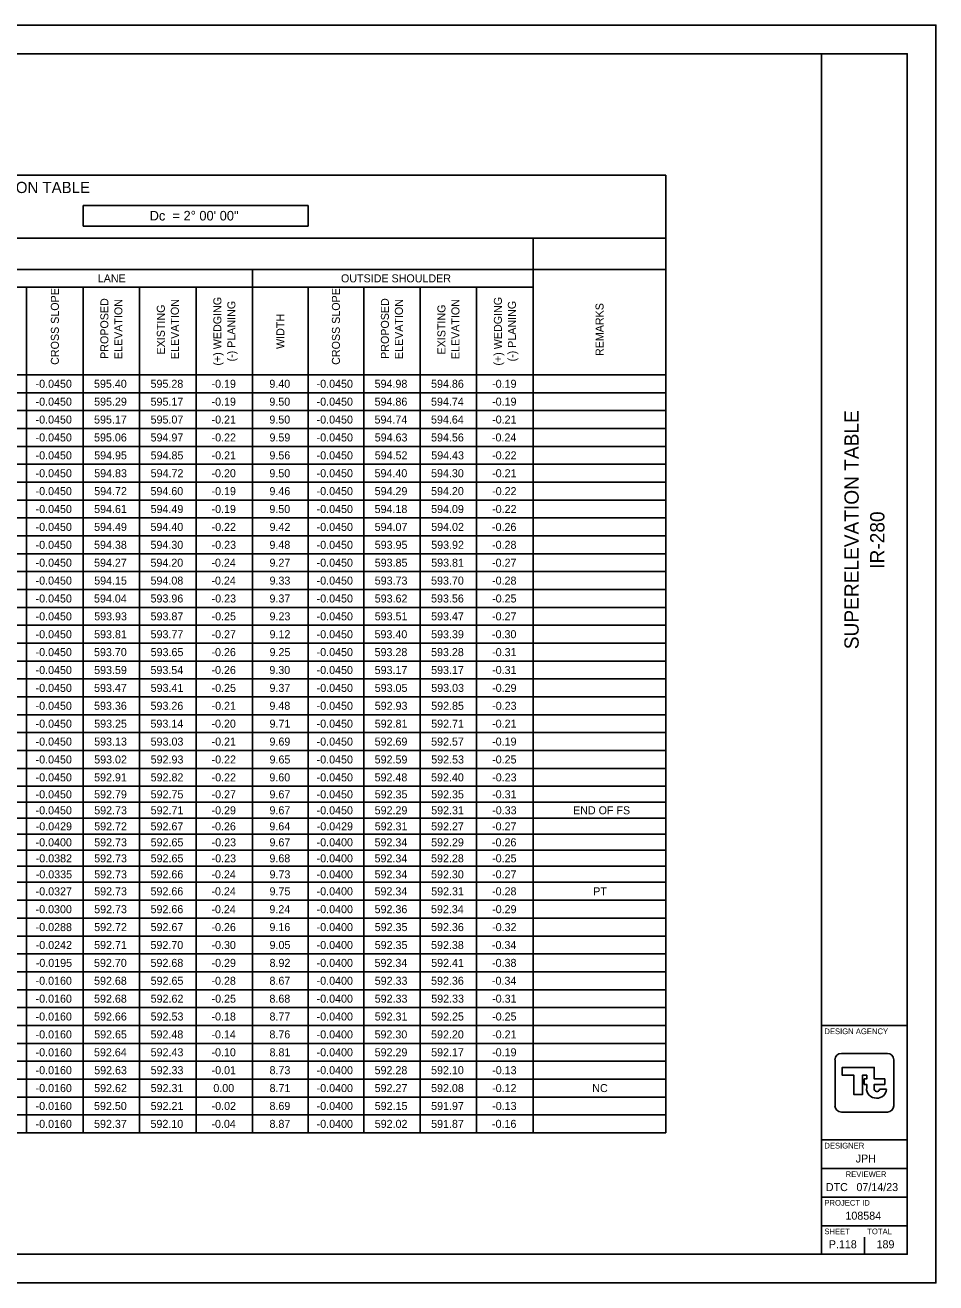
# Model space of a CAD drawing. Extents: x 0 to 34, y 0 to 22.
# Drawn here: x 18.07 to 34, y 0 to 22 of the extents above; entities that cross this region are included whole.
import ezdxf

# ---------------------------------------------------------------- set-up
doc = ezdxf.new("R2010")
doc.units = 0
for name, color, linetype in [('SH_Border', 7, 'Continuous'), ('SH_Cut_Line', 7, 'Continuous'), ('SH_Data', 7, 'Continuous'), ('SH_Text', 7, 'Continuous')]:
    doc.layers.add(name, color=color, linetype=linetype)

msp = doc.modelspace()

# ---------------------------------------------------------------- linework, layer by layer
at = {"layer": 'SH_Border'}
for p, q in [((32, 0.5), (32, 21.5)), ((32, 4.5), (33.5, 4.5)), ((32, 2.5), (33.5, 2.5)), ((32, 2), (33.5, 2)), ((32, 1.5), (33.5, 1.5)), ((32, 1), (33.5, 1))]:
    msp.add_line(p, q, dxfattribs=at)
msp.add_lwpolyline([(1.5, 21.5), (33.5, 21.5), (33.5, 0.5), (1.5, 0.5)], close=True, dxfattribs=at)
at = {"layer": 'SH_Cut_Line'}
msp.add_lwpolyline([(0, 0), (34, 0), (34, 22), (0, 22)], close=True, dxfattribs=at)
at = {"layer": 'SH_Data'}
for p, q in [((32.75, 3.5), (32.75, 3.5)), ((32.791, 3.415), (32.791, 3.415)), ((33.136, 3.385), (33.015, 3.385)), ((32.375, 0.675), (32.375, 0.675)), ((32.75, 0.5), (32.75, 0.8))]:
    msp.add_line(p, q, dxfattribs=at)
for points in [[(32.348, 4.014), (33.152, 4.014)], [(32.236, 3.099), (32.236, 3.901)], [(32.922, 3.399), (32.922, 3.47), (33.107, 3.47), (33.107, 3.568), (32.922, 3.568), (32.922, 3.768), (32.361, 3.768), (32.361, 3.632), (32.566, 3.632), (32.566, 3.294), (32.715, 3.294), (32.715, 3.63), (32.79, 3.63), (32.79, 3.568), (32.748, 3.568), (32.748, 3.47), (32.79, 3.47), (32.79, 3.415), (32.791, 3.415)], [(33.264, 3.901), (33.264, 3.099)], [(33.152, 2.986), (32.348, 2.986)]]:
    msp.add_lwpolyline(points, dxfattribs=at)
for centre, radius, start, end in [((32.348, 3.901), 0.113, 90, 180), ((33.152, 3.901), 0.113, 360, 90), ((32.949, 3.392), 0.16, 171.8856, 274.8323), ((32.968, 3.392), 0.0473, 171.8856, 350.9243), ((32.976, 3.392), 0.16, 265.1677, 357.3201), ((32.348, 3.099), 0.113, 180, 270), ((33.152, 3.099), 0.113, 270, 360)]:
    msp.add_arc(centre, radius, start, end, dxfattribs=at)
at = {"layer": 'SH_Text'}
for p, q in [((4.225, 19.375), (29.277, 19.375)), ((29.277, 19.375), (29.277, 2.624)), ((19.081, 18.848), (23.018, 18.848)), ((19.081, 18.848), (19.081, 18.486)), ((23.018, 18.848), (23.018, 18.486)), ((19.081, 18.486), (23.018, 18.486)), ((4.225, 18.271), (29.277, 18.271)), ((26.954, 18.271), (26.954, 2.624)), ((4.225, 17.728), (29.277, 17.728)), ((22.046, 17.728), (22.046, 2.624)), ((6.317, 17.415), (26.954, 17.415)), ((18.093, 17.415), (18.093, 2.624)), ((19.081, 17.415), (19.081, 2.624)), ((20.07, 17.415), (20.07, 2.624)), ((21.058, 17.415), (21.058, 2.624)), ((23.018, 17.415), (23.018, 2.624)), ((23.99, 17.415), (23.99, 2.624)), ((24.978, 17.415), (24.978, 2.624)), ((25.966, 17.415), (25.966, 2.624)), ((4.225, 15.883), (29.277, 15.883)), ((4.225, 15.57), (29.277, 15.57)), ((4.225, 15.257), (29.277, 15.257)), ((4.225, 14.944), (29.277, 14.944)), ((4.225, 14.631), (29.277, 14.631)), ((4.225, 14.319), (29.277, 14.319)), ((4.225, 14.006), (29.277, 14.006)), ((4.225, 13.693), (29.277, 13.693)), ((4.225, 13.38), (29.277, 13.38)), ((4.225, 13.067), (29.277, 13.067)), ((4.225, 12.754), (29.277, 12.754)), ((4.225, 12.441), (29.277, 12.441)), ((4.225, 12.128), (29.277, 12.128)), ((4.225, 11.815), (29.277, 11.815)), ((4.225, 11.502), (29.277, 11.502)), ((4.225, 11.189), (29.277, 11.189)), ((4.225, 10.876), (29.277, 10.876)), ((4.225, 10.563), (29.277, 10.563)), ((4.225, 10.25), (29.277, 10.25)), ((4.225, 9.937), (29.277, 9.937)), ((4.225, 9.624), (29.277, 9.624)), ((4.225, 9.311), (29.277, 9.311)), ((4.225, 8.999), (29.277, 8.999)), ((4.225, 8.686), (29.277, 8.686)), ((4.225, 8.406), (29.277, 8.406)), ((4.225, 8.126), (29.277, 8.126)), ((4.225, 7.846), (29.277, 7.846)), ((4.225, 7.566), (29.277, 7.566)), ((4.225, 7.286), (29.277, 7.286)), ((4.225, 7.006), (29.277, 7.006)), ((4.225, 6.693), (29.277, 6.693)), ((4.225, 6.38), (29.277, 6.38)), ((4.225, 6.067), (29.277, 6.067)), ((4.225, 5.754), (29.277, 5.754)), ((4.225, 5.441), (29.277, 5.441)), ((4.225, 5.128), (29.277, 5.128)), ((4.225, 4.815), (29.277, 4.815)), ((4.225, 4.502), (29.277, 4.502)), ((4.225, 4.189), (29.277, 4.189)), ((4.225, 3.876), (29.277, 3.876)), ((4.225, 3.563), (29.277, 3.563)), ((4.225, 3.25), (29.277, 3.25)), ((4.225, 2.937), (29.277, 2.937)), ((4.225, 2.624), (29.277, 2.624))]:
    msp.add_line(p, q, dxfattribs=at)

# ---------------------------------------------------------------- texts
at = {"layer": 'SH_Data'}
for s, p in [('SUPERELEVATION TABLE', (32.65, 11.084)), ('IR-280', (33.1, 12.491))]:
    msp.add_text(s, height=0.25, rotation=90, dxfattribs=at).set_placement(p)
for s, height, p in [('DESIGN AGENCY', 0.1, (32.05, 4.35)), ('DESIGNER', 0.1, (32.05, 2.35)), ('JPH', 0.14, (32.598, 2.105)), ('REVIEWER', 0.1, (32.422, 1.85)), ('DTC', 0.14, (32.076, 1.605)), ('07/14/23', 0.14, (32.611, 1.605)), ('PROJECT ID', 0.1, (32.05, 1.35)), ('108584', 0.14, (32.418, 1.105)), ('SHEET', 0.1, (32.05, 0.85)), ('TOTAL', 0.1, (32.8, 0.85)), ('P.118', 0.14, (32.127, 0.605)), ('189', 0.14, (32.963, 0.605))]:
    msp.add_text(s, height=height, dxfattribs=at).set_placement(p)
at = {"layer": 'SH_Text'}
for s, height, p in [('WOO/LUC-280-06.20/00.00 - SUPERELEVATION TABLE', 0.196, (12.442, 19.063)), ('Dc  = 2° 00\' 00"', 0.168, (20.245, 18.583)), ('LANE', 0.14, (19.338, 17.501)), ('OUTSIDE SHOULDER', 0.14, (23.593, 17.501)), ('-0.0450', 0.14, (18.25, 15.657)), ('595.40', 0.14, (19.272, 15.657)), ('595.28', 0.14, (20.261, 15.657)), ('-0.19', 0.14, (21.328, 15.657)), ('9.40', 0.14, (22.34, 15.657)), ('-0.0450', 0.14, (23.167, 15.657)), ('594.98', 0.14, (24.181, 15.657)), ('594.86', 0.14, (25.169, 15.657)), ('-0.19', 0.14, (26.237, 15.657)), ('-0.0450', 0.14, (18.25, 15.344)), ('595.29', 0.14, (19.274, 15.344)), ('595.17', 0.14, (20.262, 15.344)), ('-0.19', 0.14, (21.328, 15.344)), ('9.50', 0.14, (22.34, 15.344)), ('-0.0450', 0.14, (23.167, 15.344)), ('594.86', 0.14, (24.181, 15.344)), ('594.74', 0.14, (25.168, 15.344)), ('-0.19', 0.14, (26.237, 15.344)), ('-0.0450', 0.14, (18.25, 15.031)), ('595.17', 0.14, (19.273, 15.031)), ('595.07', 0.14, (20.262, 15.031)), ('-0.21', 0.14, (21.329, 15.031)), ('9.50', 0.14, (22.34, 15.031)), ('-0.0450', 0.14, (23.167, 15.031)), ('594.74', 0.14, (24.18, 15.031)), ('594.64', 0.14, (25.168, 15.031)), ('-0.21', 0.14, (26.237, 15.031)), ('-0.0450', 0.14, (18.25, 14.718)), ('595.06', 0.14, (19.273, 14.718)), ('594.97', 0.14, (20.262, 14.718)), ('-0.22', 0.14, (21.329, 14.718)), ('9.59', 0.14, (22.342, 14.718)), ('-0.0450', 0.14, (23.167, 14.718)), ('594.63', 0.14, (24.183, 14.718)), ('594.56', 0.14, (25.169, 14.718)), ('-0.24', 0.14, (26.234, 14.718)), ('-0.0450', 0.14, (18.25, 14.405)), ('594.95', 0.14, (19.275, 14.405)), ('594.85', 0.14, (20.263, 14.405)), ('-0.21', 0.14, (21.329, 14.405)), ('9.56', 0.14, (22.341, 14.405)), ('-0.0450', 0.14, (23.167, 14.405)), ('594.52', 0.14, (24.183, 14.405)), ('594.43', 0.14, (25.172, 14.405)), ('-0.22', 0.14, (26.237, 14.405)), ('-0.0450', 0.14, (18.25, 14.092)), ('594.83', 0.14, (19.275, 14.092)), ('594.72', 0.14, (20.263, 14.092)), ('-0.20', 0.14, (21.327, 14.092)), ('9.50', 0.14, (22.34, 14.092)), ('-0.0450', 0.14, (23.167, 14.092)), ('594.40', 0.14, (24.18, 14.092)), ('594.30', 0.14, (25.169, 14.092)), ('-0.21', 0.14, (26.237, 14.092)), ('-0.0450', 0.14, (18.25, 13.779)), ('594.72', 0.14, (19.275, 13.779)), ('594.60', 0.14, (20.26, 13.779)), ('-0.19', 0.14, (21.328, 13.779)), ('9.46', 0.14, (22.341, 13.779)), ('-0.0450', 0.14, (23.167, 13.779)), ('594.29', 0.14, (24.182, 13.779)), ('594.20', 0.14, (25.169, 13.779)), ('-0.22', 0.14, (26.237, 13.779)), ('-0.0450', 0.14, (18.25, 13.466)), ('594.61', 0.14, (19.274, 13.466)), ('594.49', 0.14, (20.262, 13.466)), ('-0.19', 0.14, (21.328, 13.466)), ('9.50', 0.14, (22.34, 13.466)), ('-0.0450', 0.14, (23.167, 13.466)), ('594.18', 0.14, (24.181, 13.466)), ('594.09', 0.14, (25.17, 13.466)), ('-0.22', 0.14, (26.237, 13.466)), ('-0.0450', 0.14, (18.25, 13.153)), ('594.49', 0.14, (19.274, 13.153)), ('594.40', 0.14, (20.26, 13.153)), ('-0.22', 0.14, (21.329, 13.153)), ('9.42', 0.14, (22.343, 13.153)), ('-0.0450', 0.14, (23.167, 13.153)), ('594.07', 0.14, (24.182, 13.153)), ('594.02', 0.14, (25.171, 13.153)), ('-0.26', 0.14, (26.235, 13.153)), ('-0.0450', 0.14, (18.25, 12.84)), ('594.38', 0.14, (19.273, 12.84)), ('594.30', 0.14, (20.26, 12.84)), ('-0.23', 0.14, (21.33, 12.84)), ('9.48', 0.14, (22.341, 12.84)), ('-0.0450', 0.14, (23.167, 12.84)), ('593.95', 0.14, (24.183, 12.84)), ('593.92', 0.14, (25.171, 12.84)), ('-0.28', 0.14, (26.236, 12.84)), ('-0.0450', 0.14, (18.25, 12.527)), ('594.27', 0.14, (19.273, 12.527)), ('594.20', 0.14, (20.26, 12.527)), ('-0.24', 0.14, (21.326, 12.527)), ('9.27', 0.14, (22.342, 12.527)), ('-0.0450', 0.14, (23.167, 12.527)), ('593.85', 0.14, (24.183, 12.527)), ('593.81', 0.14, (25.171, 12.527)), ('-0.27', 0.14, (26.236, 12.527)), ('-0.0450', 0.14, (18.25, 12.214)), ('594.15', 0.14, (19.275, 12.214)), ('594.08', 0.14, (20.261, 12.214)), ('-0.24', 0.14, (21.326, 12.214)), ('9.33', 0.14, (22.343, 12.214)), ('-0.0450', 0.14, (23.167, 12.214)), ('593.73', 0.14, (24.183, 12.214)), ('593.70', 0.14, (25.169, 12.214)), ('-0.28', 0.14, (26.236, 12.214)), ('-0.0450', 0.14, (18.25, 11.901)), ('594.04', 0.14, (19.272, 11.901)), ('593.96', 0.14, (20.261, 11.901)), ('-0.23', 0.14, (21.33, 11.901)), ('9.37', 0.14, (22.342, 11.901)), ('-0.0450', 0.14, (23.167, 11.901)), ('593.62', 0.14, (24.183, 11.901)), ('593.56', 0.14, (25.169, 11.901)), ('-0.25', 0.14, (26.237, 11.901)), ('-0.0450', 0.14, (18.25, 11.589)), ('593.93', 0.14, (19.275, 11.589)), ('593.87', 0.14, (20.262, 11.589)), ('-0.25', 0.14, (21.329, 11.589)), ('9.23', 0.14, (22.343, 11.589)), ('-0.0450', 0.14, (23.167, 11.589)), ('593.51', 0.14, (24.183, 11.589)), ('593.47', 0.14, (25.17, 11.589)), ('-0.27', 0.14, (26.236, 11.589)), ('-0.0450', 0.14, (18.25, 11.276)), ('593.81', 0.14, (19.274, 11.276)), ('593.77', 0.14, (20.262, 11.276)), ('-0.27', 0.14, (21.328, 11.276)), ('9.12', 0.14, (22.343, 11.276)), ('-0.0450', 0.14, (23.167, 11.276)), ('593.40', 0.14, (24.18, 11.276)), ('593.39', 0.14, (25.17, 11.276)), ('-0.30', 0.14, (26.235, 11.276)), ('-0.0450', 0.14, (18.25, 10.963)), ('593.70', 0.14, (19.272, 10.963)), ('593.65', 0.14, (20.263, 10.963)), ('-0.26', 0.14, (21.327, 10.963)), ('9.25', 0.14, (22.343, 10.963)), ('-0.0450', 0.14, (23.167, 10.963)), ('593.28', 0.14, (24.181, 10.963)), ('593.28', 0.14, (25.169, 10.963)), ('-0.31', 0.14, (26.237, 10.963)), ('-0.0450', 0.14, (18.25, 10.65)), ('593.59', 0.14, (19.274, 10.65)), ('593.54', 0.14, (20.26, 10.65)), ('-0.26', 0.14, (21.327, 10.65)), ('9.30', 0.14, (22.34, 10.65)), ('-0.0450', 0.14, (23.167, 10.65)), ('593.17', 0.14, (24.182, 10.65)), ('593.17', 0.14, (25.17, 10.65)), ('-0.31', 0.14, (26.237, 10.65)), ('-0.0450', 0.14, (18.25, 10.337)), ('593.47', 0.14, (19.273, 10.337)), ('593.41', 0.14, (20.263, 10.337)), ('-0.25', 0.14, (21.329, 10.337)), ('9.37', 0.14, (22.342, 10.337)), ('-0.0450', 0.14, (23.167, 10.337)), ('593.05', 0.14, (24.183, 10.337)), ('593.03', 0.14, (25.172, 10.337)), ('-0.29', 0.14, (26.237, 10.337)), ('-0.0450', 0.14, (18.25, 10.024)), ('593.36', 0.14, (19.273, 10.024)), ('593.26', 0.14, (20.261, 10.024)), ('-0.21', 0.14, (21.329, 10.024)), ('9.48', 0.14, (22.341, 10.024)), ('-0.0450', 0.14, (23.167, 10.024)), ('592.93', 0.14, (24.183, 10.024)), ('592.85', 0.14, (25.171, 10.024)), ('-0.23', 0.14, (26.238, 10.024)), ('-0.0450', 0.14, (18.25, 9.711)), ('593.25', 0.14, (19.275, 9.711)), ('593.14', 0.14, (20.26, 9.711)), ('-0.20', 0.14, (21.327, 9.711)), ('9.71', 0.14, (22.343, 9.711)), ('-0.0450', 0.14, (23.167, 9.711)), ('592.81', 0.14, (24.183, 9.711)), ('592.71', 0.14, (25.171, 9.711)), ('-0.21', 0.14, (26.237, 9.711)), ('-0.0450', 0.14, (18.25, 9.398)), ('593.13', 0.14, (19.275, 9.398)), ('593.03', 0.14, (20.263, 9.398)), ('-0.21', 0.14, (21.329, 9.398)), ('9.69', 0.14, (22.342, 9.398)), ('-0.0450', 0.14, (23.167, 9.398)), ('592.69', 0.14, (24.182, 9.398)), ('592.57', 0.14, (25.17, 9.398)), ('-0.19', 0.14, (26.237, 9.398)), ('-0.0450', 0.14, (18.25, 9.085)), ('593.02', 0.14, (19.275, 9.085)), ('592.93', 0.14, (20.263, 9.085)), ('-0.22', 0.14, (21.329, 9.085)), ('9.65', 0.14, (22.343, 9.085)), ('-0.0450', 0.14, (23.167, 9.085)), ('592.59', 0.14, (24.182, 9.085)), ('592.53', 0.14, (25.172, 9.085)), ('-0.25', 0.14, (26.237, 9.085)), ('-0.0450', 0.14, (18.25, 8.772)), ('592.91', 0.14, (19.274, 8.772)), ('592.82', 0.14, (20.263, 8.772)), ('-0.22', 0.14, (21.329, 8.772)), ('9.60', 0.14, (22.34, 8.772)), ('-0.0450', 0.14, (23.167, 8.772)), ('592.48', 0.14, (24.181, 8.772)), ('592.40', 0.14, (25.169, 8.772)), ('-0.23', 0.14, (26.238, 8.772)), ('-0.0450', 0.14, (18.25, 8.476)), ('592.79', 0.14, (19.274, 8.476)), ('592.75', 0.14, (20.263, 8.476)), ('-0.27', 0.14, (21.328, 8.476)), ('9.67', 0.14, (22.342, 8.476)), ('-0.0450', 0.14, (23.167, 8.476)), ('592.35', 0.14, (24.183, 8.476)), ('592.35', 0.14, (25.171, 8.476)), ('-0.31', 0.14, (26.237, 8.476)), ('-0.0450', 0.14, (18.25, 8.196)), ('592.73', 0.14, (19.275, 8.196)), ('592.71', 0.14, (20.263, 8.196)), ('-0.29', 0.14, (21.328, 8.196)), ('9.67', 0.14, (22.342, 8.196)), ('-0.0450', 0.14, (23.167, 8.196)), ('592.29', 0.14, (24.182, 8.196)), ('592.31', 0.14, (25.171, 8.196)), ('-0.33', 0.14, (26.238, 8.196)), ('END OF FS', 0.14, (27.653, 8.196)), ('-0.0429', 0.14, (18.252, 7.916)), ('592.72', 0.14, (19.275, 7.916)), ('592.67', 0.14, (20.262, 7.916)), ('-0.26', 0.14, (21.327, 7.916)), ('9.64', 0.14, (22.34, 7.916)), ('-0.0429', 0.14, (23.168, 7.916)), ('592.31', 0.14, (24.183, 7.916)), ('592.27', 0.14, (25.17, 7.916)), ('-0.27', 0.14, (26.236, 7.916)), ('-0.0400', 0.14, (18.25, 7.636)), ('592.73', 0.14, (19.275, 7.636)), ('592.65', 0.14, (20.263, 7.636)), ('-0.23', 0.14, (21.33, 7.636)), ('9.67', 0.14, (22.342, 7.636)), ('-0.0400', 0.14, (23.167, 7.636)), ('592.34', 0.14, (24.18, 7.636)), ('592.29', 0.14, (25.17, 7.636)), ('-0.26', 0.14, (26.235, 7.636)), ('-0.0382', 0.14, (18.252, 7.356)), ('592.73', 0.14, (19.275, 7.356)), ('592.65', 0.14, (20.263, 7.356)), ('-0.23', 0.14, (21.33, 7.356)), ('9.68', 0.14, (22.341, 7.356)), ('-0.0400', 0.14, (23.167, 7.356)), ('592.34', 0.14, (24.18, 7.356)), ('592.28', 0.14, (25.169, 7.356)), ('-0.25', 0.14, (26.237, 7.356)), ('-0.0335', 0.14, (18.253, 7.076)), ('592.73', 0.14, (19.275, 7.076)), ('592.66', 0.14, (20.261, 7.076)), ('-0.24', 0.14, (21.326, 7.076)), ('9.73', 0.14, (22.343, 7.076)), ('-0.0400', 0.14, (23.167, 7.076)), ('592.34', 0.14, (24.18, 7.076)), ('592.30', 0.14, (25.169, 7.076)), ('-0.27', 0.14, (26.236, 7.076)), ('-0.0327', 0.14, (18.251, 6.779)), ('592.73', 0.14, (19.275, 6.779)), ('592.66', 0.14, (20.261, 6.779)), ('-0.24', 0.14, (21.326, 6.779)), ('9.75', 0.14, (22.343, 6.779)), ('-0.0400', 0.14, (23.167, 6.779)), ('592.34', 0.14, (24.18, 6.779)), ('592.31', 0.14, (25.171, 6.779)), ('-0.28', 0.14, (26.236, 6.779)), ('PT', 0.14, (28.006, 6.779)), ('-0.0300', 0.14, (18.25, 6.466)), ('592.73', 0.14, (19.275, 6.466)), ('592.66', 0.14, (20.261, 6.466)), ('-0.24', 0.14, (21.326, 6.466)), ('9.24', 0.14, (22.34, 6.466)), ('-0.0400', 0.14, (23.167, 6.466)), ('592.36', 0.14, (24.181, 6.466)), ('592.34', 0.14, (25.168, 6.466)), ('-0.29', 0.14, (26.237, 6.466)), ('-0.0288', 0.14, (18.251, 6.153)), ('592.72', 0.14, (19.275, 6.153)), ('592.67', 0.14, (20.262, 6.153)), ('-0.26', 0.14, (21.327, 6.153)), ('9.16', 0.14, (22.341, 6.153)), ('-0.0400', 0.14, (23.167, 6.153)), ('592.35', 0.14, (24.183, 6.153)), ('592.36', 0.14, (25.169, 6.153)), ('-0.32', 0.14, (26.237, 6.153)), ('-0.0242', 0.14, (18.252, 5.84)), ('592.71', 0.14, (19.274, 5.84)), ('592.70', 0.14, (20.26, 5.84)), ('-0.30', 0.14, (21.327, 5.84)), ('9.05', 0.14, (22.343, 5.84)), ('-0.0400', 0.14, (23.167, 5.84)), ('592.35', 0.14, (24.183, 5.84)), ('592.38', 0.14, (25.169, 5.84)), ('-0.34', 0.14, (26.234, 5.84)), ('-0.0195', 0.14, (18.253, 5.527)), ('592.70', 0.14, (19.272, 5.527)), ('592.68', 0.14, (20.261, 5.527)), ('-0.29', 0.14, (21.328, 5.527)), ('8.92', 0.14, (22.343, 5.527)), ('-0.0400', 0.14, (23.167, 5.527)), ('592.34', 0.14, (24.18, 5.527)), ('592.41', 0.14, (25.171, 5.527)), ('-0.38', 0.14, (26.236, 5.527)), ('-0.0160', 0.14, (18.25, 5.214)), ('592.68', 0.14, (19.273, 5.214)), ('592.65', 0.14, (20.263, 5.214)), ('-0.28', 0.14, (21.327, 5.214)), ('8.67', 0.14, (22.342, 5.214)), ('-0.0400', 0.14, (23.167, 5.214)), ('592.33', 0.14, (24.183, 5.214)), ('592.36', 0.14, (25.169, 5.214)), ('-0.34', 0.14, (26.234, 5.214)), ('-0.0160', 0.14, (18.25, 4.901)), ('592.68', 0.14, (19.273, 4.901)), ('592.62', 0.14, (20.263, 4.901)), ('-0.25', 0.14, (21.329, 4.901)), ('8.68', 0.14, (22.341, 4.901)), ('-0.0400', 0.14, (23.167, 4.901)), ('592.33', 0.14, (24.183, 4.901)), ('592.33', 0.14, (25.172, 4.901)), ('-0.31', 0.14, (26.237, 4.901)), ('-0.0160', 0.14, (18.25, 4.589)), ('592.66', 0.14, (19.273, 4.589)), ('592.53', 0.14, (20.263, 4.589)), ('-0.18', 0.14, (21.327, 4.589)), ('8.77', 0.14, (22.342, 4.589)), ('-0.0400', 0.14, (23.167, 4.589)), ('592.31', 0.14, (24.183, 4.589)), ('592.25', 0.14, (25.171, 4.589)), ('-0.25', 0.14, (26.237, 4.589)), ('-0.0160', 0.14, (18.25, 4.276)), ('592.65', 0.14, (19.275, 4.276)), ('592.48', 0.14, (20.261, 4.276)), ('-0.14', 0.14, (21.326, 4.276)), ('8.76', 0.14, (22.341, 4.276)), ('-0.0400', 0.14, (23.167, 4.276)), ('592.30', 0.14, (24.18, 4.276)), ('592.20', 0.14, (25.169, 4.276)), ('-0.21', 0.14, (26.237, 4.276)), ('-0.0160', 0.14, (18.25, 3.963)), ('592.64', 0.14, (19.272, 3.963)), ('592.43', 0.14, (20.263, 3.963)), ('-0.10', 0.14, (21.327, 3.963)), ('8.81', 0.14, (22.343, 3.963)), ('-0.0400', 0.14, (23.167, 3.963)), ('592.29', 0.14, (24.182, 3.963)), ('592.17', 0.14, (25.17, 3.963)), ('-0.19', 0.14, (26.237, 3.963)), ('-0.0160', 0.14, (18.25, 3.65)), ('592.63', 0.14, (19.275, 3.65)), ('592.33', 0.14, (20.263, 3.65)), ('-0.01', 0.14, (21.329, 3.65)), ('8.73', 0.14, (22.343, 3.65)), ('-0.0400', 0.14, (23.167, 3.65)), ('592.28', 0.14, (24.181, 3.65)), ('592.10', 0.14, (25.169, 3.65)), ('-0.13', 0.14, (26.238, 3.65)), ('-0.0160', 0.14, (18.25, 3.337)), ('592.62', 0.14, (19.275, 3.337)), ('592.31', 0.14, (20.263, 3.337)), ('0.00', 0.14, (21.36, 3.337)), ('8.71', 0.14, (22.343, 3.337)), ('-0.0400', 0.14, (23.167, 3.337)), ('592.27', 0.14, (24.182, 3.337)), ('592.08', 0.14, (25.169, 3.337)), ('-0.12', 0.14, (26.237, 3.337)), ('NC', 0.14, (27.989, 3.337)), ('-0.0160', 0.14, (18.25, 3.024)), ('592.50', 0.14, (19.272, 3.024)), ('592.21', 0.14, (20.263, 3.024)), ('-0.02', 0.14, (21.329, 3.024)), ('8.69', 0.14, (22.342, 3.024)), ('-0.0400', 0.14, (23.167, 3.024)), ('592.15', 0.14, (24.183, 3.024)), ('591.97', 0.14, (25.17, 3.024)), ('-0.13', 0.14, (26.238, 3.024)), ('-0.0160', 0.14, (18.25, 2.711)), ('592.37', 0.14, (19.273, 2.711)), ('592.10', 0.14, (20.26, 2.711)), ('-0.04', 0.14, (21.326, 2.711)), ('8.87', 0.14, (22.342, 2.711)), ('-0.0400', 0.14, (23.167, 2.711)), ('592.02', 0.14, (24.183, 2.711)), ('591.87', 0.14, (25.17, 2.711)), ('-0.16', 0.14, (26.235, 2.711))]:
    msp.add_text(s, height=height, dxfattribs=at).set_placement(p)
for s, p in [('CROSS SLOPE', (18.657, 16.058)), ('CROSS SLOPE', (23.574, 16.058)), ('PROPOSED ', (19.523, 16.162)), ('ELEVATION', (19.768, 16.158)), ('ELEVATION', (20.756, 16.158)), ('(+) WEDGING', (21.5, 16.045)), ('(-) PLANING', (21.745, 16.117)), ('PROPOSED ', (24.431, 16.162)), ('ELEVATION', (24.676, 16.158)), ('ELEVATION', (25.665, 16.158)), ('(+) WEDGING', (26.408, 16.045)), ('(-) PLANING', (26.653, 16.117)), ('EXISTING ', (20.511, 16.24)), ('EXISTING ', (25.42, 16.24)), ('REMARKS', (28.186, 16.212)), ('WIDTH', (22.602, 16.336))]:
    msp.add_text(s, height=0.14, rotation=90, dxfattribs=at).set_placement(p)

doc.saveas('drawing.dxf')
